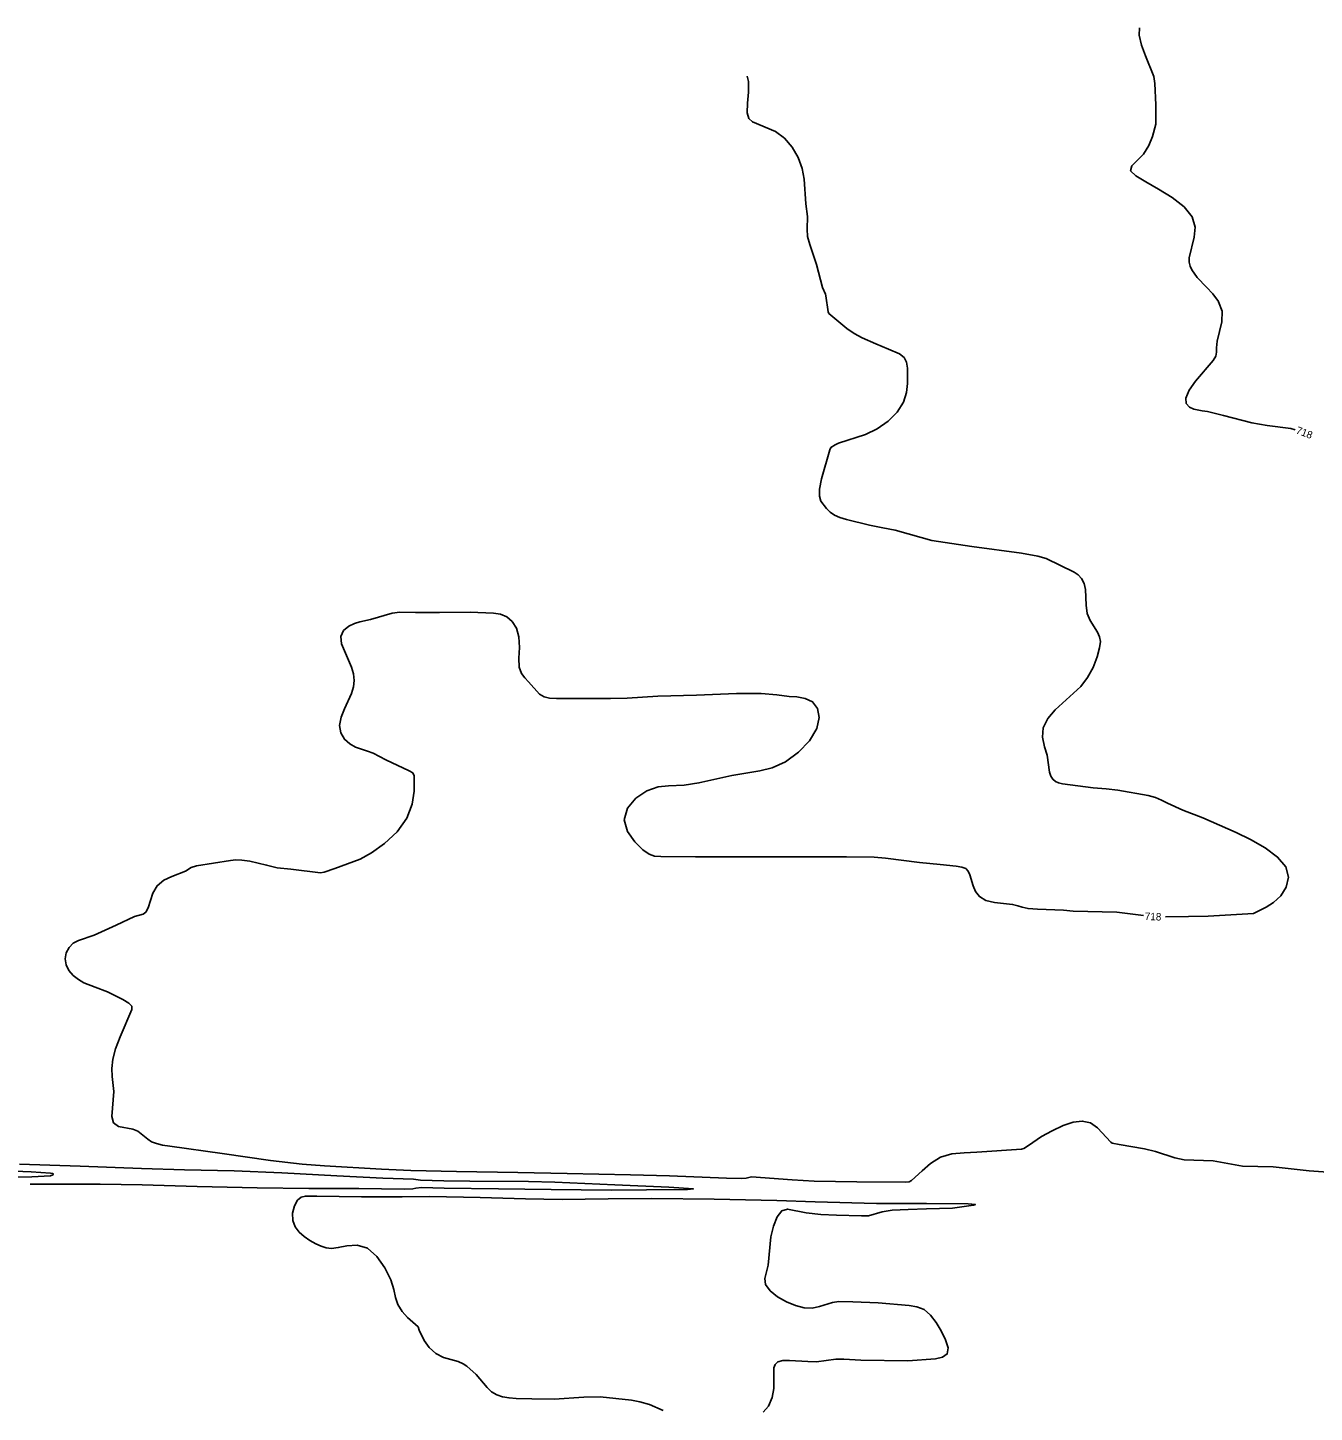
# Model space of a CAD drawing. Extents: x -361782338 to 28259792, y -263199453 to 8342113.
# Drawn here: x 1401491 to 1402184, y 576306 to 577052 of the extents above; entities that cross this region are included whole.
import ezdxf

# ---------------------------------------------------------------- set-up
doc = ezdxf.new("R2010")
doc.units = 0
doc.layers.add('DT_X_Contour_Minor', color=7, linetype='Continuous')
doc.layers.add('Level 19', color=7, linetype='Continuous')

msp = doc.modelspace()

# ---------------------------------------------------------------- linework, layer by layer
at = {"layer": 'DT_X_Contour_Minor'}
for points in [[(1402090.17, 577051.51), (1402090.1, 577047.51), (1402091.37, 577042.12), (1402093.47, 577036.32), (1402097.99, 577025.16), (1402098.52, 577021.51), (1402099.04, 577009.89), (1402099.03, 576999.53), (1402097.15, 576992.96), (1402095.15, 576988.03), (1402092.32, 576983.37), (1402086.01, 576977.02), (1402085.42, 576974.49), (1402088.18, 576971.68), (1402093.6, 576968.42), (1402100.51, 576964.58), (1402107.77, 576960.09), (1402114.18, 576955.06), (1402118.56, 576949.62), (1402120.13, 576944), (1402119.71, 576938.61), (1402117.02, 576927.51), (1402116.99, 576925.23), (1402117.47, 576923.14), (1402118.39, 576921.13), (1402121.33, 576917.01), (1402126.24, 576911.73), (1402129.65, 576908.17), (1402132.7, 576904.05)], [(1401878.91, 577025.45), (1401879.59, 577022.45), (1401879.53, 577016.8), (1401879.06, 577010.78), (1401878.94, 577005.7), (1401879.78, 577002.52), (1401881.77, 577000.73), (1401894.11, 576995.54), (1401898.92, 576992.07), (1401903.09, 576987.25), (1401906.35, 576981.55), (1401908.53, 576975.62), (1401909.55, 576970.01), (1401910.48, 576956.56), (1401911.36, 576949.88), (1401911.16, 576943.05), (1401911.48, 576939.13), (1401912.61, 576934.68), (1401916.23, 576923.93), (1401919.54, 576911.6), (1401921.01, 576907.93)], [(1402104.3, 576572.61), (1402116.52, 576572.74), (1402127.27, 576572.92), (1402151.65, 576574.49), (1402158.37, 576577.8), (1402162.41, 576580.4), (1402166.3, 576584.01), (1402169.25, 576588.68), (1402170.43, 576594.02), (1402169.03, 576599.55), (1402164.58, 576604.85), (1402157.87, 576609.76), (1402150.07, 576614.2), (1402142.28, 576618.05), (1402124.38, 576626), (1402113.57, 576630.03), (1402105.3, 576633.89), (1402102.12, 576635.54), (1402098.78, 576636.91), (1402094.82, 576637.97), (1402078.63, 576640.79), (1402072.3, 576641.54), (1402065.32, 576642.12), (1402048.78, 576644.32), (1402046.59, 576644.75), (1402044.95, 576645.48), (1402043.59, 576646.7), (1402042.52, 576648.39), (1402041.82, 576650.48), (1402040.45, 576659.65), (1402039.1, 576664.22), (1402038.01, 576669.32), (1402038.3, 576674.5), (1402040.78, 576679.44), (1402044.87, 576684.05), (1402058.61, 576696.68), (1402062.28, 576701.45), (1402065.22, 576706.98), (1402067.35, 576712.61), (1402068.65, 576717.46), (1402069.12, 576720.92), (1402068.75, 576723.48), (1402067.57, 576725.89), (1402063.65, 576732.17), (1402062.1, 576736.09), (1402061.49, 576740.42), (1402061.21, 576748.85), (1402060.42, 576752.19), (1402059.03, 576754.83), (1402057.17, 576756.84), (1402054.96, 576758.33), (1402039.89, 576765.58), (1402035.44, 576766.83), (1402026.74, 576768.45), (1401999.9, 576772.13), (1401978.42, 576775.4), (1401972.66, 576776.98), (1401958.68, 576780.93), (1401951.95, 576782.17), (1401944.87, 576783.5), (1401932.33, 576786.55), (1401928.85, 576787.63), (1401925.9, 576788.96), (1401923.52, 576790.65), (1401921.6, 576792.58), (1401918.62, 576796.56), (1401917.77, 576799.13), (1401917.8, 576803), (1401918.87, 576808.49), (1401923.34, 576824.24), (1401924, 576825.36), (1401926.27, 576826.91), (1401928.08, 576827.71), (1401942.56, 576832.35), (1401948.99, 576835.4), (1401954.85, 576839.57), (1401959.65, 576844.52), (1401963.02, 576849.78), (1401964.73, 576854.94), (1401965.27, 576859.81), (1401965.21, 576868.11), (1401964.76, 576871.36), (1401963.44, 576873.95), (1401960.96, 576875.87), (1401954.96, 576878.32), (1401948.26, 576881.19), (1401940.76, 576884.48), (1401936.51, 576886.8), (1401932.54, 576889.54), (1401922.85, 576897.59), (1401922.57, 576898.42), (1401921.2, 576907.04), (1401921.01, 576907.93)], [(1402132.68, 576904.05), (1402132.81, 576903.86), (1402134.69, 576898.82), (1402134.57, 576893.14), (1402132.04, 576882.63), (1402131.68, 576879.17), (1402131.73, 576876.69), (1402131.35, 576874.57), (1402129.89, 576872.22), (1402120.31, 576861.09), (1402116.96, 576856.29), (1402115.08, 576852.06), (1402115.36, 576849.03), (1402117.15, 576847.1), (1402119.49, 576846.03), (1402123.91, 576845.2), (1402126.87, 576844.73), (1402135.45, 576842.66), (1402150.77, 576838.77), (1402158.95, 576837.31), (1402171.76, 576835.58), (1402174.03, 576834.97)], [(1401681.94, 576436.75), (1401651.32, 576438.45), (1401639.17, 576439.43), (1401622.12, 576441.47), (1401596.2, 576445.19), (1401567.96, 576449.16), (1401564.07, 576449.72), (1401560.7, 576450.48), (1401558.06, 576451.52), (1401556.02, 576452.81), (1401550.8, 576457.15), (1401548.03, 576458.21), (1401540.32, 576459.78), (1401537.52, 576461.69), (1401536.68, 576465.11), (1401537.72, 576478.53), (1401536.83, 576486.65), (1401536.73, 576491), (1401537.29, 576495.89), (1401538.73, 576501.55), (1401541.15, 576508.02), (1401547.55, 576522.71), (1401547.44, 576524.54), (1401545.79, 576526.05), (1401542.61, 576528.03), (1401534.4, 576532.22), (1401527.73, 576534.71), (1401521.7, 576537.1), (1401518.68, 576538.83), (1401515.93, 576541.03), (1401513.64, 576543.72), (1401512.08, 576546.77), (1401511.51, 576550), (1401512.09, 576553.21), (1401513.65, 576556.1), (1401515.93, 576558.37), (1401518.77, 576559.87), (1401527.12, 576562.8), (1401539.08, 576568.23), (1401549, 576572.84), (1401553.55, 576574.02), (1401554.96, 576575.16), (1401556.26, 576577.42), (1401558.78, 576585.38), (1401561.13, 576589.4), (1401564.79, 576592.38), (1401568.98, 576594.41), (1401576.42, 576597.29), (1401579.52, 576599.26), (1401582.38, 576600.04), (1401600.68, 576602.98), (1401603.43, 576603.33), (1401606.65, 576603.22), (1401611.1, 576602.53), (1401620.08, 576600.53), (1401625.7, 576599.11), (1401633.17, 576598.37), (1401649.13, 576596.35), (1401651.09, 576596.61), (1401656.82, 576598.61), (1401670.42, 576603.78), (1401676.59, 576607.16), (1401683.57, 576612.14), (1401690.33, 576618.47), (1401695.62, 576625.7), (1401698.52, 576633.3), (1401699.58, 576640.31), (1401699.57, 576648.66), (1401698.8, 576650.13), (1401696.79, 576651.25), (1401684.26, 576657.24), (1401677.49, 576660.7), (1401674.5, 576661.94), (1401667.98, 576664.05), (1401664.81, 576665.73), (1401662.05, 576668.3), (1401660.11, 576671.67), (1401659.42, 576675.67), (1401660.24, 576680.1), (1401662.03, 576684.66), (1401665.74, 576692.96), (1401666.82, 576696.57), (1401667.21, 576700), (1401666.82, 576703.43), (1401665.73, 576707.04), (1401660.43, 576719.71), (1401660.07, 576723.67), (1401661.56, 576726.84), (1401664.31, 576729.16), (1401667.43, 576730.68), (1401670.26, 576731.51), (1401675.97, 576732.73), (1401687.62, 576736.25), (1401691.77, 576736.71), (1401700.2, 576736.59), (1401713.2, 576736.51), (1401729.63, 576736.64), (1401742.28, 576736.18), (1401746.02, 576735.58), (1401749.42, 576734.21), (1401752.4, 576731.73)], [(1401752.4, 576731.73), (1401754.7, 576728.11), (1401756.01, 576723.39), (1401756.23, 576717.73), (1401755.99, 576711.97), (1401756.14, 576707.06), (1401757.28, 576703.67), (1401759.14, 576701.34), (1401761.21, 576699.29), (1401767.02, 576692.54), (1401769.48, 576691.19), (1401772.5, 576690.45), (1401776.19, 576690.17), (1401805.35, 576690.19), (1401814.34, 576690.46), (1401830.81, 576691.54), (1401851.59, 576691.94), (1401873.14, 576693), (1401886.52, 576692.92), (1401894.85, 576692.28), (1401901.51, 576691.39), (1401905.72, 576691.06), (1401910.18, 576690.28), (1401914.12, 576688.39), (1401916.82, 576684.88), (1401917.73, 576679.97), (1401916.36, 576674.02), (1401912.43, 576667.5), (1401906.56, 576661.24), (1401899.59, 576656.18), (1401892.35, 576652.96), (1401885.7, 576651.25), (1401870.6, 576648.71), (1401852.95, 576644.74), (1401844.93, 576643.46), (1401836.48, 576643.27), (1401830.92, 576642.59), (1401824.91, 576640.53), (1401819.02, 576636.55), (1401814.47, 576631.11), (1401812.64, 576624.91), (1401814.39, 576618.65), (1401818.38, 576613.05), (1401822.74, 576608.79), (1401826.08, 576606.38), (1401828.98, 576605.36), (1401832.48, 576605.09), (1401851, 576604.96), (1401876.01, 576604.96), (1401903.96, 576604.97), (1401932.47, 576604.96)], [(1401932.47, 576604.96), (1401947.34, 576604.82), (1401953.46, 576604.3), (1401971.75, 576601.98), (1401982.8, 576600.89), (1401991.46, 576600), (1401994.54, 576599.47), (1401996.61, 576598.67), (1401997.96, 576597.3), (1401998.89, 576595.17), (1402000.56, 576589.39), (1402001.87, 576586.3), (1402003.99, 576583.52), (1402007.38, 576581.43), (1402012.19, 576580.28), (1402021.89, 576579.28), (1402024.73, 576578.59), (1402026.99, 576577.77), (1402030.19, 576577.08), (1402035.3, 576576.69), (1402049.2, 576576.16), (1402054.54, 576575.72), (1402078.06, 576575.07), (1402092.32, 576573.36)], [(1402191.67, 576435.12), (1402181.6, 576435.9), (1402162.27, 576438.07), (1402145.68, 576438.36), (1402129.83, 576441.18), (1402114.29, 576441.72), (1402109.31, 576442.83), (1402098.81, 576446.17), (1402092.91, 576447.62), (1402079.22, 576450.09), (1402075.57, 576450.69), (1402074.76, 576451.28), (1402067.66, 576459.02), (1402063.74, 576461.61), (1402059.35, 576462.61), (1402054.47, 576462.05), (1402049.03, 576460.21), (1402043.11, 576457.42), (1402037.47, 576454.3), (1402030.36, 576449.56), (1402028, 576447.78), (1402026.66, 576447.51), (1402002.61, 576445.85), (1401995.73, 576445.61), (1401989.12, 576444.96), (1401983.01, 576443.16), (1401977.63, 576439.83), (1401973.15, 576435.85), (1401967.48, 576430.54), (1401966.1, 576429.83), (1401964.43, 576429.73), (1401938.05, 576429.95), (1401915.07, 576430.3), (1401903.1, 576430.92), (1401881.19, 576432.52), (1401878.36, 576431.97), (1401875.74, 576431.76), (1401867.82, 576431.84), (1401837.07, 576433.11), (1401815.99, 576433.66), (1401781.98, 576434.46), (1401755.34, 576434.99), (1401722.28, 576435.42), (1401697.77, 576435.93), (1401681.94, 576436.75)], [(1401486.93, 576439.5), (1401519.72, 576438.32), (1401552.71, 576437.17), (1401575.92, 576436.4), (1401602.54, 576435.76), (1401628.3, 576434.83), (1401657.9, 576433.15), (1401682.59, 576431.81)], [(1401469.54, 576432.36), (1401493.6, 576432.61), (1401503.64, 576433.2), (1401504.97, 576433.62), (1401505.17, 576434.02), (1401504.98, 576434.35), (1401503.62, 576434.64), (1401493.27, 576435.31), (1401461.98, 576436.59)], [(1401682.59, 576431.81), (1401699.11, 576431.27), (1401702.91, 576430.85), (1401715.5, 576430.37), (1401729.54, 576430.2), (1401761.16, 576430.07), (1401775.27, 576429.67), (1401807.56, 576428.33), (1401836.7, 576427.08), (1401849.94, 576426.07), (1401846.84, 576425.77), (1401824.67, 576425.54), (1401805.69, 576425.5), (1401773.27, 576425.76), (1401745.01, 576426.16), (1401715.68, 576426.51), (1401703.44, 576426.77), (1401700.39, 576426.42), (1401698.79, 576426.08), (1401694.19, 576426.02), (1401669.79, 576426.27), (1401642.75, 576426.37), (1401615, 576426.73), (1401582.64, 576427.48), (1401552.97, 576428.22), (1401530.37, 576428.62), (1401500.21, 576428.64), (1401492.7, 576428.58)], [(1401833.67, 576306.69), (1401826.33, 576309.92), (1401821.18, 576311.5), (1401816.63, 576312.32), (1401799.78, 576314.2), (1401791, 576313.98), (1401774.9, 576312.87), (1401762.9, 576313.02), (1401754.55, 576313.23), (1401750.64, 576313.54), (1401747.11, 576314.14), (1401744, 576315.19), (1401741.27, 576316.82), (1401738.9, 576319.11), (1401732.97, 576326.17), (1401727.84, 576330.66), (1401725.91, 576331.96), (1401723.24, 576333.08), (1401715.36, 576335.25), (1401711.22, 576337.37), (1401707.68, 576340.69), (1401704.93, 576344.51), (1401702.17, 576350.05), (1401701.64, 576351.79), (1401695.91, 576356.83), (1401693.09, 576360.13), (1401690.8, 576363.82), (1401689.51, 576367.64), (1401688.54, 576371.93), (1401686.89, 576377.19), (1401683.82, 576383.55), (1401679.51, 576389.76), (1401674.35, 576394.22), (1401668.79, 576395.81), (1401663.37, 576395.44), (1401658.66, 576394.48), (1401655.04, 576394.08), (1401652.16, 576394.37), (1401649.45, 576395.25), (1401646.51, 576396.59), (1401643.4, 576398.34), (1401640.34, 576400.44), (1401637.56, 576402.86), (1401635.38, 576405.71), (1401634.14, 576409.13), (1401634.07, 576413.09), (1401635.01, 576416.99), (1401636.67, 576420.03), (1401638.77, 576421.68), (1401640.96, 576422.25), (1401647.08, 576422.23), (1401671.2, 576421.9), (1401693.03, 576421.82), (1401707.9, 576422.05), (1401735.13, 576421.51), (1401759.44, 576420.81), (1401779.21, 576420.38), (1401803.95, 576420.78), (1401827.53, 576420.92), (1401861.19, 576420.59), (1401894.96, 576419.81), (1401915.52, 576419.17), (1401948.53, 576418.2), (1401975.49, 576418.18), (1401997.94, 576418.03), (1402001.87, 576417.63), (1402000.74, 576417.26), (1401989.53, 576415.65), (1401975.48, 576415.28), (1401965.54, 576415.07), (1401956.94, 576414.63), (1401951.63, 576413.83), (1401944.23, 576411.65), (1401940.46, 576411.53), (1401927.1, 576411.87), (1401918.51, 576412.38), (1401910.67, 576413.29), (1401900.65, 576415.26), (1401897.55, 576414.36), (1401895, 576411.09), (1401893, 576406.09), (1401891.68, 576400.35), (1401890.18, 576384.96), (1401888.37, 576377.83), (1401888.85, 576374.62), (1401891.31, 576371.29), (1401895.28, 576368.05), (1401900.02, 576365.27), (1401904.86, 576363.24), (1401909.56, 576362.09), (1401913.93, 576361.92), (1401917.89, 576362.68), (1401924.92, 576364.97), (1401928.3, 576365.44), (1401935.76, 576365.27), (1401949.43, 576364.79), (1401966.19, 576363.29), (1401970.36, 576362.64), (1401974.26, 576361.07), (1401977.72, 576358.18), (1401980.76, 576354.24)], [(1401980.76, 576354.24), (1401983.46, 576349.65), (1401985.77, 576344.88), (1401987.08, 576340.52), (1401986.7, 576337.22), (1401984.19, 576335.41), (1401980.34, 576334.67), (1401965.51, 576333.5), (1401940.18, 576333.94), (1401930.93, 576334.49), (1401926.58, 576334.48), (1401916.16, 576332.97), (1401911.52, 576333.09), (1401901.74, 576333.76), (1401898.05, 576333.6), (1401895.47, 576332.9), (1401893.93, 576331.61), (1401893.33, 576329.69), (1401893.2, 576318.69), (1401892.34, 576313.7), (1401890.4, 576309.09), (1401887.57, 576305.78)]]:
    msp.add_lwpolyline(points, dxfattribs=at)

# ---------------------------------------------------------------- texts
at = {"layer": 'Level 19'}
for rotation, p in [(339.25977, (1402174.14, 576833.12)), (357.60015, (1402092.98, 576570.98))]:
    msp.add_text('718', height=4, rotation=rotation, dxfattribs=at).set_placement(p)

doc.saveas('drawing.dxf')
